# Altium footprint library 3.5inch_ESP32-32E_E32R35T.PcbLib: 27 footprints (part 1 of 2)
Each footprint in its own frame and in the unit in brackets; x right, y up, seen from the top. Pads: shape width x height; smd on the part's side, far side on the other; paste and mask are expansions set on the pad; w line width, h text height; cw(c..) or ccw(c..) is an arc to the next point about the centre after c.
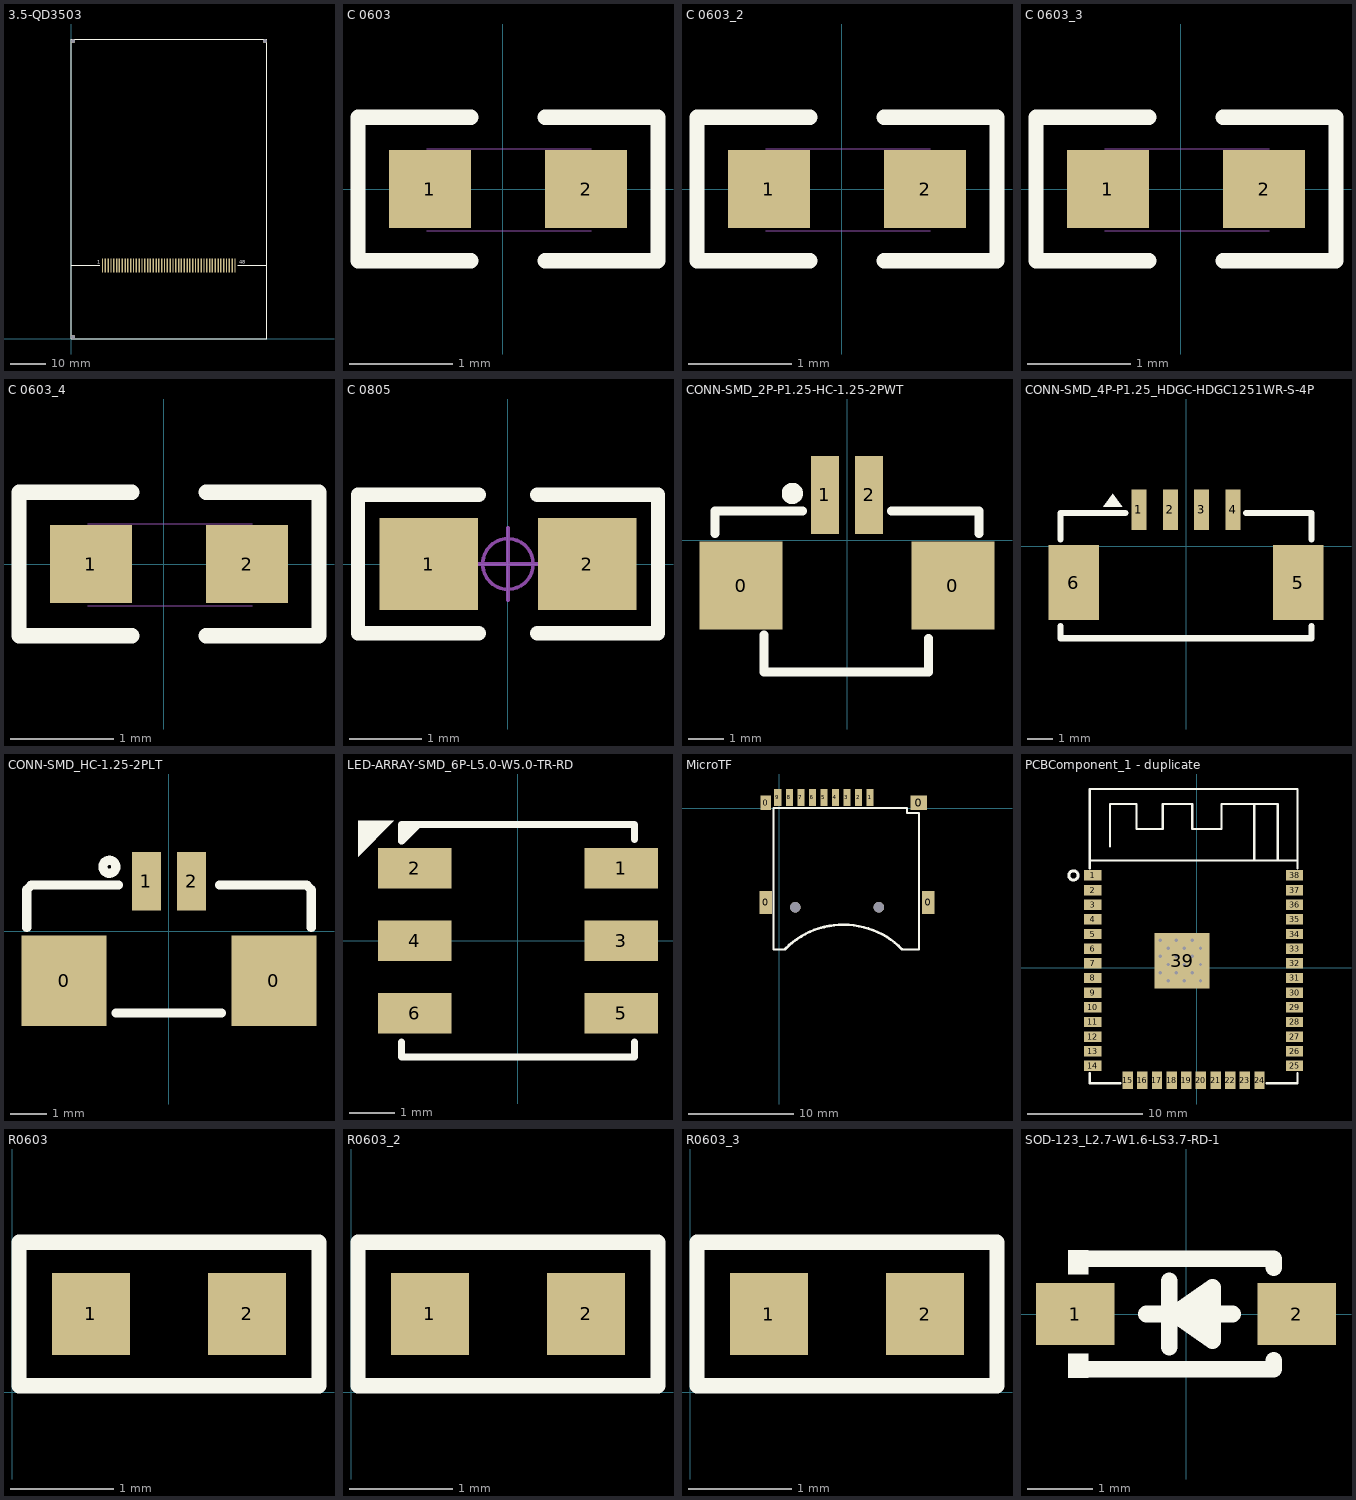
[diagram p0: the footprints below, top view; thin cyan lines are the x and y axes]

## 3.5-QD3503 [mm] "3.5 TFT LCD"
pads (51):
  round 1.2 hole 1.2 unplated: 0(0.5,0.5) 0(0.5,84.46) 0(55,84.46)
  rect 0.4x4 smd: 1(8.88,20.8) 2(9.68,20.8) 3(10.48,20.8) 4(11.28,20.8) 5(12.08,20.8) 6(12.88,20.8) 7(13.68,20.8) 8(14.48,20.8) 9(15.28,20.8) 10(16.08,20.8) 11(16.88,20.8) 12(17.68,20.8) 13(18.48,20.8) 14(19.28,20.8) 15(20.08,20.8) 16(20.88,20.8) 17(21.68,20.8) 18(22.48,20.8) 19(23.28,20.8) 20(24.08,20.8) 21(24.88,20.8) 22(25.68,20.8) 23(26.48,20.8) 24(27.28,20.8) 25(28.08,20.8) 26(28.88,20.8) 27(29.68,20.8) 28(30.48,20.8) 29(31.28,20.8) 30(32.08,20.8) 31(32.88,20.8) 32(33.68,20.8) 33(34.48,20.8) 34(35.28,20.8) 35(36.08,20.8) 36(36.88,20.8) 37(37.68,20.8) 38(38.48,20.8) 39(39.28,20.8) 40(40.08,20.8) 41(40.88,20.8) 42(41.68,20.8) 43(42.48,20.8) 44(43.28,20.8) 45(44.08,20.8) 46(44.88,20.8) 47(45.68,20.8) 48(46.48,20.8)
Top Overlay:
  lines w0.254: 0.028,20.8 8.128,20.8 ; 47.232,20.8 55.5,20.8 ; 0,0 0,84.96 55.5,84.96 55.5,0 0,0
  text "48" at 47.625,21.209 h1.02
  text "1" at 7.366,21.209 h1.02

## C 0603 [mm] "无极性贴片电容"
pads (2):
  rect 0.8x0.76 smd: 1(-0.711,0) 2(0.809,0)
Top Overlay:
  lines w0.15: -0.311,-0.7 -1.411,-0.7 -1.411,0.7 -0.311,0.7 ; 0.409,-0.7 1.509,-0.7 1.509,0.7 0.409,0.7
Mechanical 13:
  lines w0.01: -0.742,-0.406 0.858,-0.406 ; -0.742,0.394 0.858,0.394
3D body "C 0603.STEP": height 0.81, standoff -0.01, extent -0.742,-0.41 0.858,0.41

## C 0603_2 [mm]
pads (2):
  rect 0.8x0.76 smd: 1(-0.711,0) 2(0.809,0)
Top Overlay:
  lines w0.15: -0.311,-0.7 -1.411,-0.7 -1.411,0.7 -0.311,0.7 ; 0.409,-0.7 1.509,-0.7 1.509,0.7 0.409,0.7
Mechanical 13:
  lines w0.01: -0.742,-0.406 0.858,-0.406 ; -0.742,0.394 0.858,0.394
3D body "C 0603.STEP": height 0.81, standoff -0.01, extent -0.742,-0.41 0.858,0.41

## C 0603_3 [mm]
pads (2):
  rect 0.8x0.76 smd: 1(-0.711,0) 2(0.809,0)
Top Overlay:
  lines w0.15: -0.311,-0.7 -1.411,-0.7 -1.411,0.7 -0.311,0.7 ; 0.409,-0.7 1.509,-0.7 1.509,0.7 0.409,0.7
Mechanical 13:
  lines w0.01: -0.742,-0.406 0.858,-0.406 ; -0.742,0.394 0.858,0.394
3D body "C 0603.STEP": height 0.81, standoff -0.01, extent -0.742,-0.41 0.858,0.41

## C 0603_4 [mm]
pads (2):
  rect 0.8x0.76 smd: 1(-0.711,0) 2(0.809,0)
Top Overlay:
  lines w0.15: -0.311,-0.7 -1.411,-0.7 -1.411,0.7 -0.311,0.7 ; 0.409,-0.7 1.509,-0.7 1.509,0.7 0.409,0.7
Mechanical 13:
  lines w0.01: -0.742,-0.406 0.858,-0.406 ; -0.742,0.394 0.858,0.394
3D body "C 0603.STEP": height 0.81, standoff -0.01, extent -0.742,-0.41 0.858,0.41

## C 0805 [mm] "无极性贴片电容"
height 0.5
pads (2):
  rect 1.36x1.27 smd: 1(-1.094,0) 2(1.094,0)
Top Overlay:
  lines w0.2: -0.406,-0.955 -2.074,-0.955 -2.074,0.955 -0.406,0.955 ; 0.406,-0.955 2.074,-0.955 ; 0.406,0.955 2.074,0.955 ; 2.075,-0.955 2.075,0.955
Mechanical 15:
  circle w0.05: c0,0 r0.35
  lines w0.05: -0.5,0 0.5,0 ; 0,-0.5 0,0.5
3D body "C 0805.STEP": height 0.51, standoff -0.01, extent -1,-0.61 1,0.61

## CONN-SMD_2P-P1.25-HC-1.25-2PWT [mm]
pads (4):
  rect 2.35x2.5 smd paste+0 mask+0.05: 0(-3.005,-1.285) 0(3.005,-1.285)
  rect 0.8x2.2 smd paste+0 mask+0.05: 1(-0.625,1.285) 2(0.625,1.285)
Top Overlay:
  circle w0.3: c-1.55,1.33 r0.15
  lines w0.254: -3.75,0.196 -3.75,0.835 -1.256,0.835 ; -2.36,-2.69 -2.36,-3.73 2.31,-3.73 2.31,-2.78 ; 1.256,0.835 3.75,0.835 3.75,0.196

## CONN-SMD_4P-P1.25_HDGC-HDGC1251WR-S-4P [mm]
pads (6):
  rect 0.6x1.6 smd mask+0.05: 1(-1.875,1.45) 2(-0.625,1.45) 3(0.625,1.45) 4(1.875,1.45)
  rect 2x3 smd mask+0.05: 5(4.475,-1.45) 6(-4.475,-1.45)
Top Overlay:
  region: -3.175,1.577 -3.302,1.577 -2.921,2.085 -2.54,1.577 -3.175,1.577
  lines w0.254: -5,-3.181 -5,-3.669 5,-3.669 5,-3.181 ; -5,0.281 -5,1.323 -2.413,1.323 ; 2.406,1.323 5,1.323 5,0.281

## CONN-SMD_HC-1.25-2PLT [mm]
pads (4):
  rect 2.35x2.5 smd paste+0 mask+0.05: 0(-2.9,-1.38) 0(2.9,-1.38)
  rect 0.8x1.62 smd paste+0 mask+0.05: 1(-0.625,1.38) 2(0.625,1.38)
Top Overlay:
  circle w0.254: c-1.651,1.778 r0.18
  lines w0.254: -3.937,0.101 -3.937,1.143 -3.81,1.27 -1.397,1.27 ; -1.47,-2.27 1.451,-2.27 ; 1.397,1.27 3.81,1.27 3.937,1.143 3.937,0.101

## LED-ARRAY-SMD_6P-L5.0-W5.0-TR-RD [mm]
pads (6):
  rect 1.625x0.896 smd mask+0.051: 1(2.288,1.6) 2(-2.288,1.6) 3(2.288,0) 4(-2.288,0) 5(2.288,-1.6) 6(-2.288,-1.6)
Top Overlay:
  region: -2.286,2.576 -2.576,2.576 -2.576,2.239 -2.497,2.239 -2.159,2.576
  region: -2.54,2.159 -2.54,2.202 -2.576,2.239
  region: -2.874,2.652 -3.54,2.652 -3.54,1.859 -2.747,2.652
  lines w0.152: -2.576,-2.239 -2.576,-2.576 2.576,-2.576 2.576,-2.239 ; -2.202,2.576 -2.576,2.202 -2.576,2.576 2.576,2.576 2.576,2.239

## MicroTF [mm]
height 2.65
pads (15):
  rect 1x1.4 smd: 0(-1.3,0.526)
  rect 1.2x2.2 smd: 0(-1.3,-8.994) 0(14.2,-8.994)
  rect 1.6x1.4 smd: 0(13.3,0.526)
  rect 0.7x1.6 smd: 1(8.65,1.026) 2(7.55,1.026) 3(6.45,1.026) 4(5.35,1.026) 5(4.25,1.026) 6(3.15,1.026) 7(2.05,1.026) 8(0.95,1.026) 9(-0.15,1.026)
  round 1 hole 1 unplated: ""(1.52,-9.474) ""(9.5,-9.474)
Top Overlay:
  lines w0.2: 0.563,-13.5 -0.559,-13.5 -0.559,0.026 12.192,0.026 ; 11.709,-13.5 13.335,-13.5 13.335,-0.483
  lines w0.203: 12.192,0.026 12.192,-0.483 13.335,-0.483
  lines w0.254: 0.563,-13.43 cw(c6.113,-18.98) 11.721,-13.489
3D body "User Library-MEM2055-00-190-01-A_revG.STEP": height 1.85, standoff -0.6, extent -1.548,-13.472 14.452,1.778

## PCBComponent_1 - duplicate [mm]
pads (39):
  rect 1.5x0.9 smd mask+0.051: 1(-9.004,7.987) 2(-9.004,6.717) 3(-9.004,5.447) 4(-9.004,4.177) 5(-9.004,2.907) 6(-9.004,1.637) 7(-9.004,0.367) 8(-9.004,-0.903) 9(-9.004,-2.173) 10(-9.004,-3.443) 11(-9.004,-4.713) 12(-9.004,-5.983) 13(-9.004,-7.253) 14(-9.004,-8.523) 25(8.496,-8.523) 26(8.496,-7.253) 27(8.496,-5.983) 28(8.496,-4.713) 29(8.496,-3.443) 30(8.496,-2.173) 31(8.496,-0.903) 32(8.496,0.367) 33(8.496,1.637) 34(8.496,2.907) 35(8.496,4.177) 36(8.496,5.447) 37(8.496,6.717) 38(8.496,7.987)
  rect 0.9x1.5 smd mask+0.051: 15(-5.969,-9.774) 16(-4.699,-9.774) 17(-3.429,-9.774) 18(-2.159,-9.774) 19(-0.889,-9.774) 20(0.381,-9.774) 21(1.651,-9.774) 22(2.921,-9.774) 23(4.191,-9.774) 24(5.461,-9.774)
  rect 4.8x4.8 smd mask+0.051: 39(-1.254,0.576)
via 0.346,-1.133 diameter 0.5 hole 0.3
via -3.154,2.367 diameter 0.5 hole 0.3
via 0.346,0.267 diameter 0.5 hole 0.3
via 0.346,1.667 diameter 0.5 hole 0.3
via -0.354,2.367 diameter 0.5 hole 0.3
via -1.754,2.367 diameter 0.5 hole 0.3
via -1.754,0.967 diameter 0.5 hole 0.3
via -1.754,-0.433 diameter 0.5 hole 0.3
via -2.454,1.667 diameter 0.5 hole 0.3
via -3.154,0.967 diameter 0.5 hole 0.3
via -3.154,-0.433 diameter 0.5 hole 0.3
via -0.354,-0.433 diameter 0.5 hole 0.3
via -0.354,0.967 diameter 0.5 hole 0.3
via -1.054,1.667 diameter 0.5 hole 0.3
via -1.054,0.267 diameter 0.5 hole 0.3
via -2.454,0.267 diameter 0.5 hole 0.3
via -2.454,-1.133 diameter 0.5 hole 0.3
via -1.054,-1.133 diameter 0.5 hole 0.3
Top Overlay:
  circle w0.254: c-10.668,7.986 r0.402
  lines w0.203: -9.254,-9.15 -9.254,-10.023 -6.596,-10.023 ; -9.254,8.613 -9.254,15.476 8.746,15.477 8.746,8.614 ; -9.254,9.287 8.746,9.287 ; -7.493,10.489 -7.493,14.172 -5.207,14.172 -5.207,12.013 -2.921,12.013 -2.921,14.172 -0.381,14.172 -0.381,12.013 2.159,12.013 2.159,14.172 5.011,14.172 5.011,9.287 ; 4.808,14.172 7.043,14.172 7.043,9.287 ; 6.088,-10.023 8.746,-10.023 8.746,-9.15
3D body "ESP32-WROOM-32E_20210903.STEP": height 3.2, standoff 0.1, extent -9.254,-10.023 8.746,15.477

## R0603 [mm]
pads (2):
  rect 0.76x0.8 smd: 1(0.766,0.762) 2(2.286,0.762)
Top Overlay:
  lines w0.15: 0.066,0.062 2.986,0.062 2.986,1.462 0.066,1.462 0.066,0.062
3D body "RES0603.STEP": height 0.65, standoff 0.2, extent 0.749,0.348 2.349,1.168

## R0603_2 [mm]
pads (2):
  rect 0.76x0.8 smd: 1(0.766,0.762) 2(2.286,0.762)
Top Overlay:
  lines w0.15: 0.066,0.062 0.066,1.462 2.986,1.462 2.986,0.062 0.066,0.062
3D body "RES0603.STEP": height 0.65, standoff 0.2, extent 0.749,0.348 2.349,1.168

## R0603_3 [mm]
pads (2):
  rect 0.76x0.8 smd: 1(0.766,0.762) 2(2.286,0.762)
Top Overlay:
  lines w0.15: 0.066,0.062 2.986,0.062 2.986,1.462 0.066,1.462 0.066,0.062
3D body "RES0603.STEP": height 0.65, standoff 0.2, extent 0.749,0.348 2.349,1.168

## SOD-123_L2.7-W1.6-LS3.7-RD-1 [mm]
pads (2):
  rect 1.2x0.95 smd: 1(-1.7,0) 2(1.7,0)
Top Overlay:
  region: -1.502,-0.977 -1.502,-0.607 -1.806,-0.607 -1.806,-0.977
  region: -1.502,0.977 -1.502,0.607 -1.806,0.607 -1.806,0.977
  region: 0.406,-0.406 0.406,0.406 -0.178,0
  lines w0.254: -1.644,0.849 -1.643,0.85 -1.346,0.85 1.346,0.85 1.346,0.706 ; -1.639,-0.849 -1.638,-0.85 -1.346,-0.85 1.346,-0.85 1.346,-0.706 ; -0.61,0 -0.28,0 ; -0.254,-0.508 -0.254,0.508 ; 0.406,0 0.72,0 ; -0.178,0 0.406,-0.406 0.406,0.406 -0.178,0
